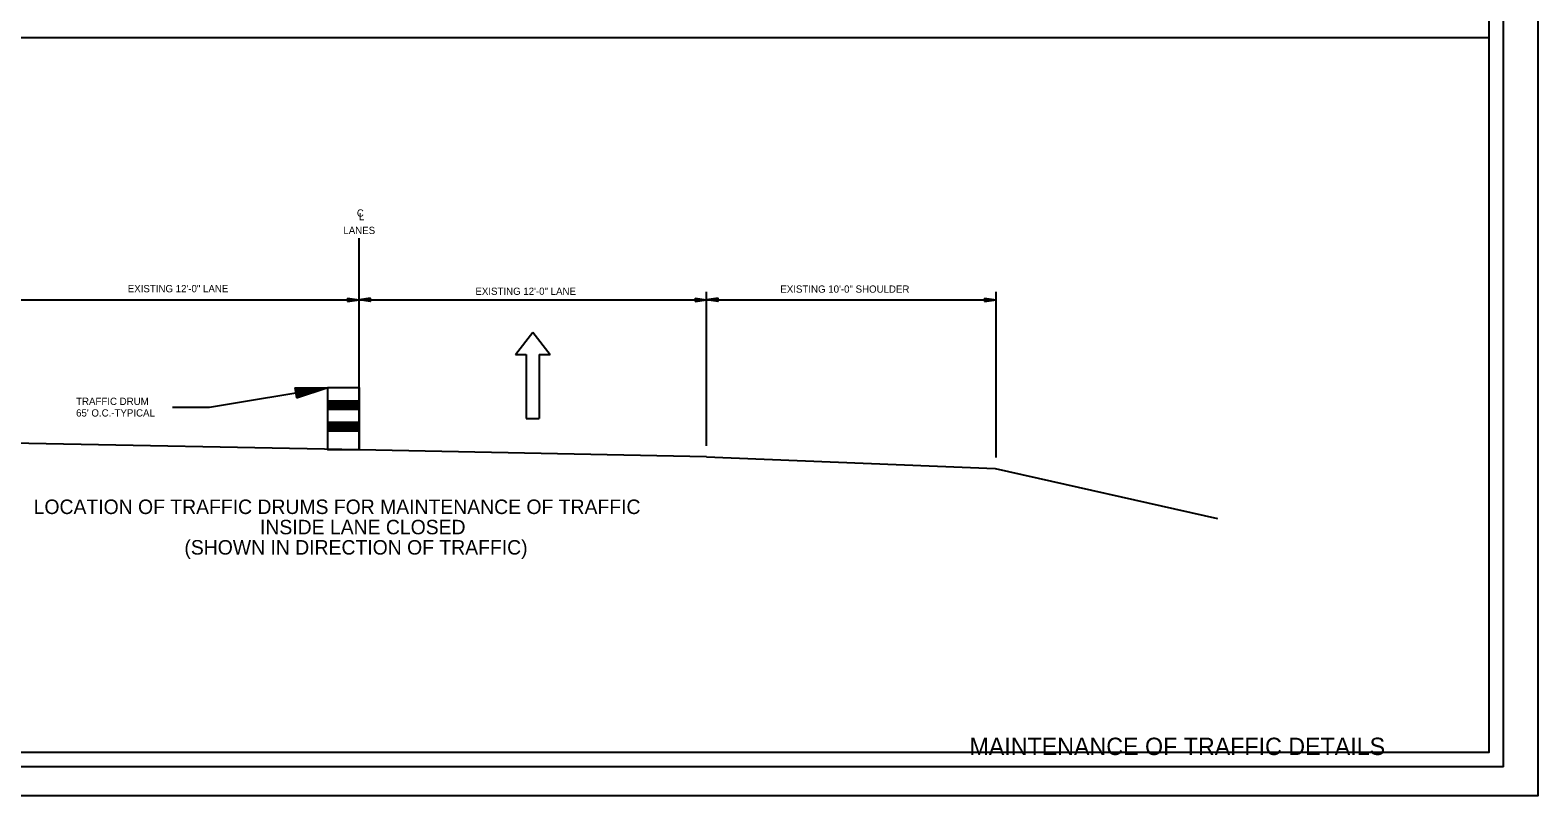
# Model space of a CAD drawing. Extents: x 13528 to 25043, y 7635 to 10612.
# Drawn here: x 20354 to 21396, y 9545 to 10073 of the extents above; entities that cross this region are included whole.
import ezdxf

# ---------------------------------------------------------------- set-up
doc = ezdxf.new("R2010")
doc.units = 0
for name, color, linetype in [('Default', 7, 'Continuous'), ('R_Border', 7, 'Continuous'), ('R_Border Plan-Plan', 7, 'Continuous'), ('R_Draft', 7, 'Continuous'), ('R_Revision Date Text', 7, 'Continuous'), ('STAMP_PE_TAEGTMEYER-SIGNATURE', 7, 'Continuous')]:
    doc.layers.add(name, color=color, linetype=linetype)

msp = doc.modelspace()

# ---------------------------------------------------------------- linework, layer by layer
at = {"layer": 'Default'}
for p, q in [((20581.4, 9783.6), (20581.4, 9929.9)), ((20821.5, 9877.6), (20821.5, 9892.7)), ((21021.5, 9879.1), (21021.5, 9892.7)), ((20341.4, 9887.2), (20581.4, 9887.2)), ((20570.8, 9887.2), (20581.4, 9887.2)), ((20573.4, 9888.4), (20581.4, 9887.2)), ((20573.4, 9888.4), (20573.4, 9886)), ((20573.4, 9888.2), (20580.1, 9887.2)), ((20573.4, 9888), (20578.7, 9887.2)), ((20573.4, 9887.8), (20577.4, 9887.2)), ((20573.4, 9887.6), (20576, 9887.2)), ((20573.4, 9887.4), (20574.7, 9887.2)), ((20573.4, 9886), (20581.4, 9887.2)), ((20573.4, 9886.8), (20576, 9887.2)), ((20573.4, 9886.4), (20578.7, 9887.2)), ((20573.4, 9886.2), (20580.1, 9887.2)), ((20573.4, 9886.6), (20577.4, 9887.2)), ((20573.4, 9887), (20574.7, 9887.2)), ((20589.4, 9888.4), (20581.4, 9887.2)), ((20581.4, 9887.2), (20821.5, 9887.2)), ((20589.4, 9886), (20581.4, 9887.2)), ((20589.4, 9888.2), (20582.8, 9887.2)), ((20589.4, 9886.2), (20582.8, 9887.2)), ((20589.4, 9888), (20584.1, 9887.2)), ((20589.4, 9886.4), (20584.1, 9887.2)), ((20589.4, 9887.8), (20585.5, 9887.2)), ((20589.4, 9886.6), (20585.5, 9887.2)), ((20589.4, 9887.6), (20586.8, 9887.2)), ((20589.4, 9886.8), (20586.8, 9887.2)), ((20589.4, 9887.4), (20588.2, 9887.2)), ((20589.4, 9887), (20588.2, 9887.2)), ((20589.4, 9886), (20589.4, 9888.4)), ((20813.5, 9888.4), (20821.5, 9887.2)), ((20813.5, 9888.4), (20813.5, 9886)), ((20813.5, 9888.2), (20820.1, 9887.2)), ((20813.5, 9888), (20818.8, 9887.2)), ((20813.5, 9887.8), (20817.4, 9887.2)), ((20813.5, 9887.6), (20816.1, 9887.2)), ((20813.5, 9887.4), (20814.7, 9887.2)), ((20813.5, 9886), (20821.5, 9887.2)), ((20813.5, 9886.8), (20816.1, 9887.2)), ((20813.5, 9886.4), (20818.8, 9887.2)), ((20813.5, 9886.2), (20820.1, 9887.2)), ((20813.5, 9886.6), (20817.4, 9887.2)), ((20813.5, 9887), (20814.7, 9887.2)), ((20829.5, 9888.4), (20821.5, 9887.2)), ((20821.5, 9887.2), (21021.5, 9887.2)), ((20829.5, 9886), (20821.5, 9887.2)), ((20829.5, 9888.2), (20822.8, 9887.2)), ((20829.5, 9886.2), (20822.8, 9887.2)), ((20829.5, 9888), (20824.2, 9887.2)), ((20829.5, 9886.4), (20824.2, 9887.2)), ((20829.5, 9887.8), (20825.5, 9887.2)), ((20829.5, 9886.6), (20825.5, 9887.2)), ((20829.5, 9887.6), (20826.9, 9887.2)), ((20829.5, 9886.8), (20826.9, 9887.2)), ((20829.5, 9887.4), (20828.2, 9887.2)), ((20829.5, 9887), (20828.2, 9887.2)), ((20829.5, 9886), (20829.5, 9888.4)), ((21013.5, 9888.4), (21021.5, 9887.2)), ((21013.5, 9888.4), (21013.5, 9886)), ((21013.5, 9888.2), (21020.2, 9887.2)), ((21013.5, 9888), (21018.8, 9887.2)), ((21013.5, 9887.8), (21017.5, 9887.2)), ((21013.5, 9887.6), (21016.1, 9887.2)), ((21013.5, 9887.4), (21014.8, 9887.2)), ((21013.5, 9886), (21021.5, 9887.2)), ((21013.5, 9886.8), (21016.1, 9887.2)), ((21013.5, 9886.4), (21018.8, 9887.2)), ((21013.5, 9886.2), (21020.2, 9887.2)), ((21013.5, 9886.6), (21017.5, 9887.2)), ((21013.5, 9887), (21014.8, 9887.2)), ((20821.5, 9786.4), (20821.5, 9877.6)), ((21021.5, 9778.4), (21021.5, 9879.1)), ((20478.1, 9813.1), (20559.8, 9826.8)), ((20452.5, 9813.1), (20478.1, 9813.1)), ((20581.4, 9783.6), (20341.4, 9788.4)), ((20821.5, 9778.8), (20581.4, 9783.6)), ((20821.5, 9778.8), (21020.8, 9770.8)), ((21020.8, 9770.8), (21174.3, 9736.4))]:
    msp.add_line(p, q, dxfattribs=at)
at = {"layer": 'R_Border'}
for p, q in [((20537.1, 9826.4), (20559.8, 9826.8)), ((20537.1, 9826.4), (20538.2, 9819.7)), ((20537.2, 9825.8), (20556.1, 9826.1)), ((20537.3, 9825.3), (20552.3, 9825.5)), ((20537.3, 9824.7), (20548.6, 9824.9)), ((20537.4, 9824.1), (20544.8, 9824.3)), ((20537.5, 9823.6), (20541.1, 9823.6)), ((20537.7, 9822.5), (20541.1, 9823.6)), ((20537.8, 9822), (20544.8, 9824.3)), ((20537.9, 9821.4), (20548.6, 9824.9)), ((20538, 9820.8), (20552.3, 9825.5)), ((20538.1, 9820.3), (20556.1, 9826.1)), ((20538.2, 9819.7), (20559.8, 9826.8)), ((20559.8, 9817.5), (20581.4, 9817.5)), ((20559.8, 9816.7), (20581.4, 9816.7)), ((20559.8, 9815.9), (20581.4, 9815.9)), ((20559.8, 9815.2), (20581.4, 9815.2)), ((20559.8, 9814.3), (20581.4, 9814.3)), ((20559.8, 9813.3), (20581.4, 9813.3)), ((20559.8, 9812.3), (20581.4, 9812.3)), ((20559.8, 9811.7), (20581.4, 9811.7)), ((20559.8, 9802.7), (20581.4, 9802.7)), ((20559.8, 9801.9), (20581.4, 9801.9)), ((20559.8, 9801.1), (20581.4, 9801.1)), ((20559.8, 9800.4), (20581.4, 9800.4)), ((20559.8, 9799.5), (20581.4, 9799.5)), ((20559.8, 9798.5), (20581.4, 9798.5)), ((20559.8, 9797.5), (20581.4, 9797.5)), ((20559.8, 9796.9), (20581.4, 9796.9))]:
    msp.add_line(p, q, dxfattribs=at)
msp.add_lwpolyline([(20559.8, 9826.8), (20581.4, 9826.8), (20581.4, 9783.6), (20559.8, 9783.6)], close=True, dxfattribs=at)
at = {"layer": 'R_Draft'}
for q in [(21371.8, 10592.1), (19790.9, 9564.8)]:
    msp.add_line((21371.8, 9564.8), q, dxfattribs=at)
at = {"layer": 'R_Revision Date Text'}
for points in [[(19728.9, 10611.5), (21395.6, 10611.5), (21395.6, 9544.9), (19728.9, 9544.9)], [(19800.9, 10582.1), (21048.6, 10582.1), (21048.6, 10532.7), (21136.3, 10532.7), (21256.8, 10532.7), (21256.8, 10421), (21361.8, 10421), (21361.8, 9574.8), (19800.9, 9574.8)], [(19800.9, 10068.4), (21361.8, 10068.4), (21361.8, 9574.8), (19800.9, 9574.8)]]:
    msp.add_lwpolyline(points, close=True, dxfattribs=at)
at = {"layer": 'STAMP_PE_TAEGTMEYER-SIGNATURE'}
for p, q in [((20689.4, 9849.5), (20701.4, 9865)), ((20701.4, 9865), (20713.5, 9849.5)), ((20689.4, 9849.5), (20696.9, 9849.5)), ((20696.9, 9849.5), (20696.9, 9805.3)), ((20705.9, 9849.5), (20705.9, 9805.3)), ((20705.9, 9849.5), (20713.5, 9849.5)), ((20696.9, 9805.3), (20705.9, 9805.3))]:
    msp.add_line(p, q, dxfattribs=at)

# ---------------------------------------------------------------- texts
at = {"layer": 'Default'}
for s, height, p in [('C', 5, (20579.9, 9944.7)), ('L', 5, (20581.4, 9942.2)), ('LANES', 5, (20570.6, 9932.7)), ('EXISTING 12\'-0" LANE', 5.001, (20421.7, 9892.5)), ('EXISTING 12\'-0" LANE', 5.001, (20661.8, 9890.7)), ('EXISTING 10\'-0" SHOULDER', 5.001, (20872.4, 9892.2)), ('LOCATION OF TRAFFIC DRUMS FOR MAINTENANCE OF TRAFFIC', 10.002, (20356.7, 9739.4)), ('INSIDE LANE CLOSED', 10.002, (20513, 9725.4)), ('(SHOWN IN DIRECTION OF TRAFFIC)', 10.002, (20460.8, 9711.4))]:
    msp.add_text(s, height=height, dxfattribs=at).set_placement(p)
for s, p in [('TRAFFIC DRUM', (20386, 9814.7)), ("65' O.C.-TYPICAL", (20386, 9806.7))]:
    msp.add_text(s, height=5.001, rotation=360, dxfattribs=at).set_placement(p)
at = {"layer": 'R_Border Plan-Plan'}
msp.add_text('MAINTENANCE OF TRAFFIC DETAILS', height=12, dxfattribs=at).set_placement((21003, 9573))

doc.saveas('drawing.dxf')
